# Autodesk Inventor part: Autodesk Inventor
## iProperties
Company: Cad-Q A/S
Title: Autodesk Inventor
Author: Administrator
Comments: Serie 42xx A og 43xx A
Shininess: 86.0
PropertySet Name: _Private Model Information
Created: 2001-03
Part Number: 4217 A
Document SubType Name: Modeling
Designer: Administrator
Description: SKF Double Row Ball Bearing,Open, 4217 A
Control State: 0
Master: False
Checked Out: False
PropertySet Name: Design Tracking Control
Density: 0.0
Volumn: 0.0
Area: 0.0
PropertySet Name: Model Information
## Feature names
1. Lagerhus [Revolution]
2. Kulespor [Revolution]
3. Kule [Revolution]
4. kule1 [Revolution]
5. Kuler [Circular Pattern]
